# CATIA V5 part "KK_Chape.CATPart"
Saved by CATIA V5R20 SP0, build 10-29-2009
Part number: chape
Bounding box of the stored display mesh (mm): x -291 to 115, y -10 to 220, z -77 to 73
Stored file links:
  G:\Khaled_CFAO_2011\ST2M\ST2M_GR2\tcorbin\Khaled\CAD_ThinkMOTION\KK_Chape.CATPart
  F:\Thinkmotionperso\assemblage robot\ass_skl_robot.CATProduct
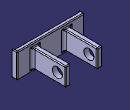
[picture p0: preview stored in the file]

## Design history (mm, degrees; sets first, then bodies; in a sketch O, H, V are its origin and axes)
External parameters (linked from other documents)
  `External.diametre perçage chape_soc` = 60 mm
  `External.hauteur chape` = 200 mm
  `External.largeur table` = 400 mm
Body1 (main body)
  Sketch1 on zx-plane, origin (0, 0, 0), H (-1, 0, 0), V (0, 0, 1)
    line L1 (-112, 73) -> (288, 73)
    line L2 (288, 73) -> (288, -77)
    line L3 (288, -77) -> (-112, -77)
    line L4 (-112, -77) -> (-112, 73)
    length L1 = 400 {= `External.largeur table`}
    length L2 = 150
    horizontal: L1 H, L3 H
    vertical: L2 V, L4 V
  Pad1: profile Sketch1, direction (0, 1, 0), length 20
  Sketch2 on end face of Pad1, origin (0, 20, 0), H (-1, 0, 0), V (0, 0, 1)
    line L1 (-23, 50) -> (7.7066, 50)
    line L2 (7.7066, 50) -> (7.7066, -60)
    line L3 (7.7066, -60) -> (-23, -60)
    line L4 (-23, -60) -> (-23, 50)
    point P5 (167.7066, 50)
    line L5 (167.7066, 50) -> (198.7066, 50)
    line L6 (198.7066, 50) -> (198.7066, -60)
    line L7 (198.7066, -60) -> (167.7066, -60)
    line L8 (167.7066, -60) -> (167.7066, 50)
    point P7 (198.7066, -60)
    distance L8 L2 = 160
    length L6 = 110
    horizontal: L1 H, L3 H, L5 H, L7 H
    vertical: L2 V, L4 V, L6 V, L8 V
    coincidence: P5 L1, P7 L3
  Pad2: profile Sketch2, direction (0, 1, 0), length 200 {= `External.hauteur chape`}
  Sketch3 on face of Pad2 from Sketch2.L4, origin (23, 195.353, -2.2613), H (0, 1, 0), V (0, 0, 1)
    point P1 (-25.353, -2.7387)
    reference projected line E1 (24.647, 52.2613) -> (24.647, -57.7387) from edge [face of Pad2 from Sketch2.L4 | end face of Pad2]
    reference projected line E2 (-175.353, 52.2613) -> (24.647, 52.2613) from edge [face of Pad2 from Sketch2.L4 | face of Pad2 from Sketch2.L1]
    distance P1 E1 = 50 {= `External.hauteur chape` -150mm}
    distance P1 E2 = 55
  Hole1: placed by Sketch3, at (23, 170, -5) direction (-1, 0, 0), diameter 60 {= `External.diametre perçage chape_soc`}, through (limit type 3)
  Sketch4 on face of Pad1 from Sketch1.L3, origin (0, 0, -77), H (1, 0, 0), V (0, -1, 0)
    line L1 (112, 10) -> (115, 10)
    line L2 (115, 10) -> (115, -20)
    line L3 (115, -20) -> (112, -20)
    line L4 (112, -20) -> (112, 10)
    reference projected line E1 (112, -20) -> (-288, -20) from edge [face of Pad1 from Sketch1.L3 | end face of Pad1]
    line L5 (-288, -20) -> (-291, -20)
    line L6 (-291, -20) -> (-291, 10)
    line L7 (-291, 10) -> (-288, 10)
    line L8 (-288, 10) -> (-288, -20)
    reference projected line E2 (112, -20) -> (-288, -20) from edge [face of Pad1 from Sketch1.L3 | end face of Pad1]
    reference projected line E3 (-288, 0) -> (-288, -20) from edge [face of Pad1 from Sketch1.L2 | face of Pad1 from Sketch1.L3]
    length L2 = 30
    length L6 = 30
    length L1 = 3
    length L7 = 3
    horizontal: L1 H, L3 H, L5 H, L7 H
    vertical: L2 V, L4 V, L6 V, L8 V
    coincidence: L3 E1, L5 E2, L8 E3
  Pad3: profile Sketch4, direction (0, 0, 1), length 150
  Fillet1: radius 5, on edge [face of Pad3 | face of Pad3]
  Fillet2: radius 5, on edge [face of Pad3 from Sketch4.L6 | face of Pad3]
  Fillet3: radius 5, on edge [face of Pad3 | face of Pad3]
  Fillet4: radius 5, on edge [face of Pad3 | face of Pad3 from Sketch4.L2]
  FaceFillet1: Radius 15, Face1 face of Pad2 from Sketch2.L4, Face2 face of Pad3, ConicRatio 0.5
  FaceFillet2: Radius 15, Face1 face of Pad2 from Sketch2.L2, Face2 face of Pad3, ConicRatio 0.5
  FaceFillet3: Radius 15, Face1 face of Pad2 from Sketch2.L6, Face2 face of Pad3, ConicRatio 0.5
  FaceFillet4: Radius 5, Face1 face of Pad2 from Sketch2.L7, Face2 face of Pad3, ConicRatio 0.5
  FaceFillet5: Radius 15, Face1 face of Pad2 from Sketch2.L8, Face2 face of Pad3, ConicRatio 0.5
  FaceFillet6: Radius 5, Face1 face of Pad2 from Sketch2.L3, Face2 face of Pad3, ConicRatio 0.5
  FaceFillet7: Radius 5, Face1 face of Pad2 from Sketch2.L1, Face2 face of Pad3, ConicRatio 0.5
  FaceFillet8: Radius 5, Face1 face of Pad2 from Sketch2.L5, Face2 face of Pad3, ConicRatio 0.5
  Fillet5: radius 5, on edge [face of Pad2 from Sketch2.L7 | face of Pad2 from Sketch2.L8]; edge [face of Pad2 from Sketch2.L7 | end face of Pad2]; edge [face of Pad2 from Sketch2.L6 | face of Pad2 from Sketch2.L7]
  Fillet6: radius 5, on edge [face of Pad2 from Sketch2.L8 | end face of Pad2]; edge [face of Pad2 from Sketch2.L6 | end face of Pad2]; edge [face of Pad2 from Sketch2.L5 | end face of Pad2]
  Fillet7: radius 5, on edge [face of Pad2 from Sketch2.L8 | face of Pad2 from Sketch2.L5]
  Fillet8: radius 5, on edge [face of Pad2 from Sketch2.L5 | face of Pad2 from Sketch2.L6]
  Fillet9: radius 5, on end face of Pad2
  Fillet10: radius 5, on edge [face of Pad2 from Sketch2.L1 | face of Pad2 from Sketch2.L2]; edge [face of Pad2 from Sketch2.L4 | face of Pad2 from Sketch2.L1]
  Fillet11: radius 5, on edge [face of Pad2 from Sketch2.L2 | face of Pad2 from Sketch2.L3]
  Fillet12: radius 5, on edge [face of Pad2 from Sketch2.L3 | face of Pad2 from Sketch2.L4]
